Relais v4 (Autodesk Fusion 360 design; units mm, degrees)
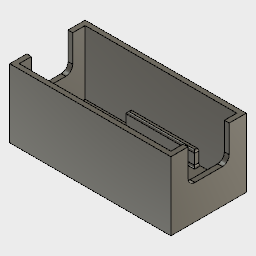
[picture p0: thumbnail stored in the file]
sketch "Skizze1"
  line L1 (23.5, 11) -> (-23.5, 11)
  line L2 (23.5, -11) -> (23.5, 11)
  line L3 (-23.5, -11) -> (23.5, -11)
  line L4 (-23.5, 11) -> (-23.5, -11)
  line L5 (23.5, -11) -> (-23.5, 11)
  line L6 (-23.5, -11) -> (23.5, 11)
  line L7 (-22.1, -9.6) -> (22.1, -9.6)
  line L8 (-22.1, 9.6) -> (-22.1, -9.6)
  line L9 (22.1, 9.6) -> (-22.1, 9.6)
  line L10 (22.1, -9.6) -> (22.1, 9.6)
  point P4 (23.5, -11)
  point P5 (-23.5, -11)
  point P3 (23.5, 11)
  dimension "d1" distance P4 P5 = 47
  dimension "d2" distance P3 P4 = 22
  dimension "d3" = 1.4
extrude "Extrusion1" new body sketch "Skizze1" profile of L1 L2 L3 L4 L8 L7 L9 L10 blind 1.4
extrude "Extrusion2" add sketch "Skizze1" profile of L1 L2 L3 L4 L8 L7 L9 L10 blind 20
sketch "Skizze2" plane through (0, 0, 20) normal (0, 0, 1) x axis (-1, 0, 0)
  line L1 (-22.1, -9.6) -> (22.1, -9.6)
  line L2 (-22.1, 9.6) -> (-22.1, -9.6)
  line L3 (22.1, 9.6) -> (-22.1, 9.6)
  line L4 (22.1, -9.6) -> (22.1, 9.6)
  line L5 (-23.5, 11) -> (23.5, 11)
  line L6 (-23.5, -11) -> (-23.5, 11)
  line L7 (23.5, -11) -> (-23.5, -11)
  line L8 (23.5, 11) -> (23.5, -11)
  line L9 (22.1, -6) -> (23.5, -6)
  line L10 (22.1, 6) -> (22.1, -6)
  line L11 (23.5, 6) -> (22.1, 6)
  line L12 (23.5, -6) -> (23.5, 6)
  line L13 (-23.5, -6) -> (-22.1, -6)
  line L14 (-23.5, 6) -> (-23.5, -6)
  line L15 (-22.1, 6) -> (-23.5, 6)
  line L16 (-22.1, -6) -> (-22.1, 6)
  point P10 (23.5, -6)
  point P13 (23.5, 6)
  point P1 (0, 0)
  dimension "d8" distance P10 P13 = 12
  dimension "d9" distance P1 L11 = 6 (= "d8 / 2")
extrude "Extrusion3" cut sketch "Skizze2" profile of L2 L4 L6 L8 L9 L10 L11 L12 L13 L14 L15 L16 against normal blind 10
fillet "Abrundung1" radius 2
sketch "Skizze3" plane through (0, 0, 1.4) normal (0, 0, 1) x axis (-1, 0, 0)
  line L1 (22.1, 9.6) -> (22.1, -9.6)
  line L2 (-22.1, 9.6) -> (22.1, 9.6)
  line L3 (-22.1, -9.6) -> (-22.1, 9.6)
  line L4 (22.1, -9.6) -> (-22.1, -9.6)
  line L5 (9, -8.4) -> (9, -9.6)
  line L6 (-11, -8.4) -> (9, -8.4)
  line L7 (-11, -9.6) -> (-11, -8.4)
  line L8 (9, 8.4) -> (9, 9.6)
  line L9 (-11, 8.4) -> (9, 8.4)
  line L10 (-11, 9.6) -> (-11, 8.4)
  line L11 (0, 9.6) -> (0, -9.6)
  line L12 (-22.1, 9.6) -> (-22.1, -9.6)
  point P11 (9, 8.4)
  point P12 (-11, 8.4)
  dimension "d13" distance L6 L9 = 16.8
  dimension "d14" distance P11 P12 = 20
  dimension "d15" distance L10 L12 = 11.1
extrude "Extrusion4" add sketch "Skizze3" profile of L2 L4 L5 L6 L7 L8 L9 L10 along normal blind 4
fillet "Abrundung2" radius 0.5
sketch "Skizze4" plane through (0, 0, 20) normal (0, 0, 1) x axis (-1, 0, 0)
  line L1 (23.5, 11) -> (23.5, 6)
  line L2 (-23.5, 11) -> (23.5, 11)
  line L3 (-23.5, 6) -> (-23.5, 11)
  line L4 (-22.1, 9.6) -> (-22.1, 6)
  line L5 (22.1, 9.6) -> (-22.1, 9.6)
  line L6 (22.1, 6) -> (22.1, 9.6)
  line L7 (-23.5, -11) -> (23.5, -11)
  line L8 (-23.5, 11) -> (-23.5, -11)
  line L9 (23.5, 11) -> (-23.5, 11)
  line L10 (23.5, -11) -> (23.5, 11)
  line L11 (23.5, 6) -> (22.1, 6)
  line L12 (-22.1, 6) -> (-23.5, 6)
extrude "Extrusion5" new body sketch "Skizze4" profile of L1 L2 L3 L4 L5 L6 L7 L8 L9 L10 along normal blind 1.4
sketch "Skizze5" plane through (0, 0, 20) normal (0, 0, -1) x axis (1, 0, 0)
  line L1 (-23.5, 11) -> (23.5, 11)
  line L2 (-23.5, -11) -> (-23.5, 11)
  line L3 (23.5, -11) -> (-23.5, -11)
  line L4 (23.5, 11) -> (23.5, -11)
  line L5 (22.1, 9.6) -> (-22.1, 9.6)
  line L6 (22.1, -9.6) -> (22.1, 9.6)
  line L7 (-22.1, -9.6) -> (22.1, -9.6)
  line L8 (-22.1, 9.6) -> (-22.1, -9.6)
  line L9 (-21.1, -8.6) -> (21.1, -8.6)
  line L10 (-21.1, 8.6) -> (-21.1, -8.6)
  line L11 (21.1, 8.6) -> (-21.1, 8.6)
  line L12 (21.1, -8.6) -> (21.1, 8.6)
  dimension "d23" = 1
extrude "Extrusion6" new body sketch "Skizze5" profile of L5 L6 L7 L8 L9 L11 L10 L12 along normal blind 1
combine "Kombinieren"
